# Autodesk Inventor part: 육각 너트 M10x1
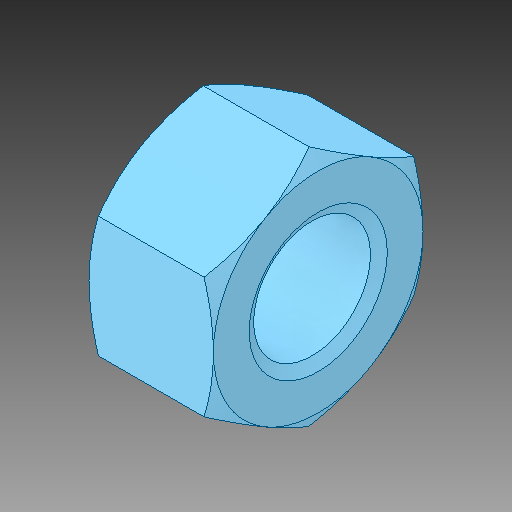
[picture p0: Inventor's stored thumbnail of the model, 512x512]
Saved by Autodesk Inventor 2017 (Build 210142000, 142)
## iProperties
Created: 2024-08
Part Number: 육각 너트 M10x1
Material: 일반
Description: 6각 너트 및 6각 가는 너트
Document SubType Name: Modeling
Designer: MRC
Density: 1 g/cm^3
Appearance: 기본값
Author: jhkim
Sending System: Autodesk Inventor 2025
Preprocessor: ST-DEVELOPER v20
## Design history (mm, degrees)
feature "Solid1"
node "솔리드1"
